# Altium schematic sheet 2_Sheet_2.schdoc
size 322 x 185 mm; Name: A_Customize; Symbol: A_Customize; Device: A_Customize; @Project Name: MyOwnMP3_PCB; REV: 1.0; Date: 2026-02-28; Sheet: 1/1; Draw By: maxyusyuk; Company: Your Company; Convert to PCB: yes; Add into BOM: yes; spicePre: .; @Page No: 2; @Page Count: 3; @Schematic Name: MyOwnMP3; @Board Name: MyOwnMP3; @Update Date: 2026-04-22; @Create Time: 17:18:59; @Update Time: 18:40:26; @Page Name: Sheet_2; @Create Date: 2026-03-28
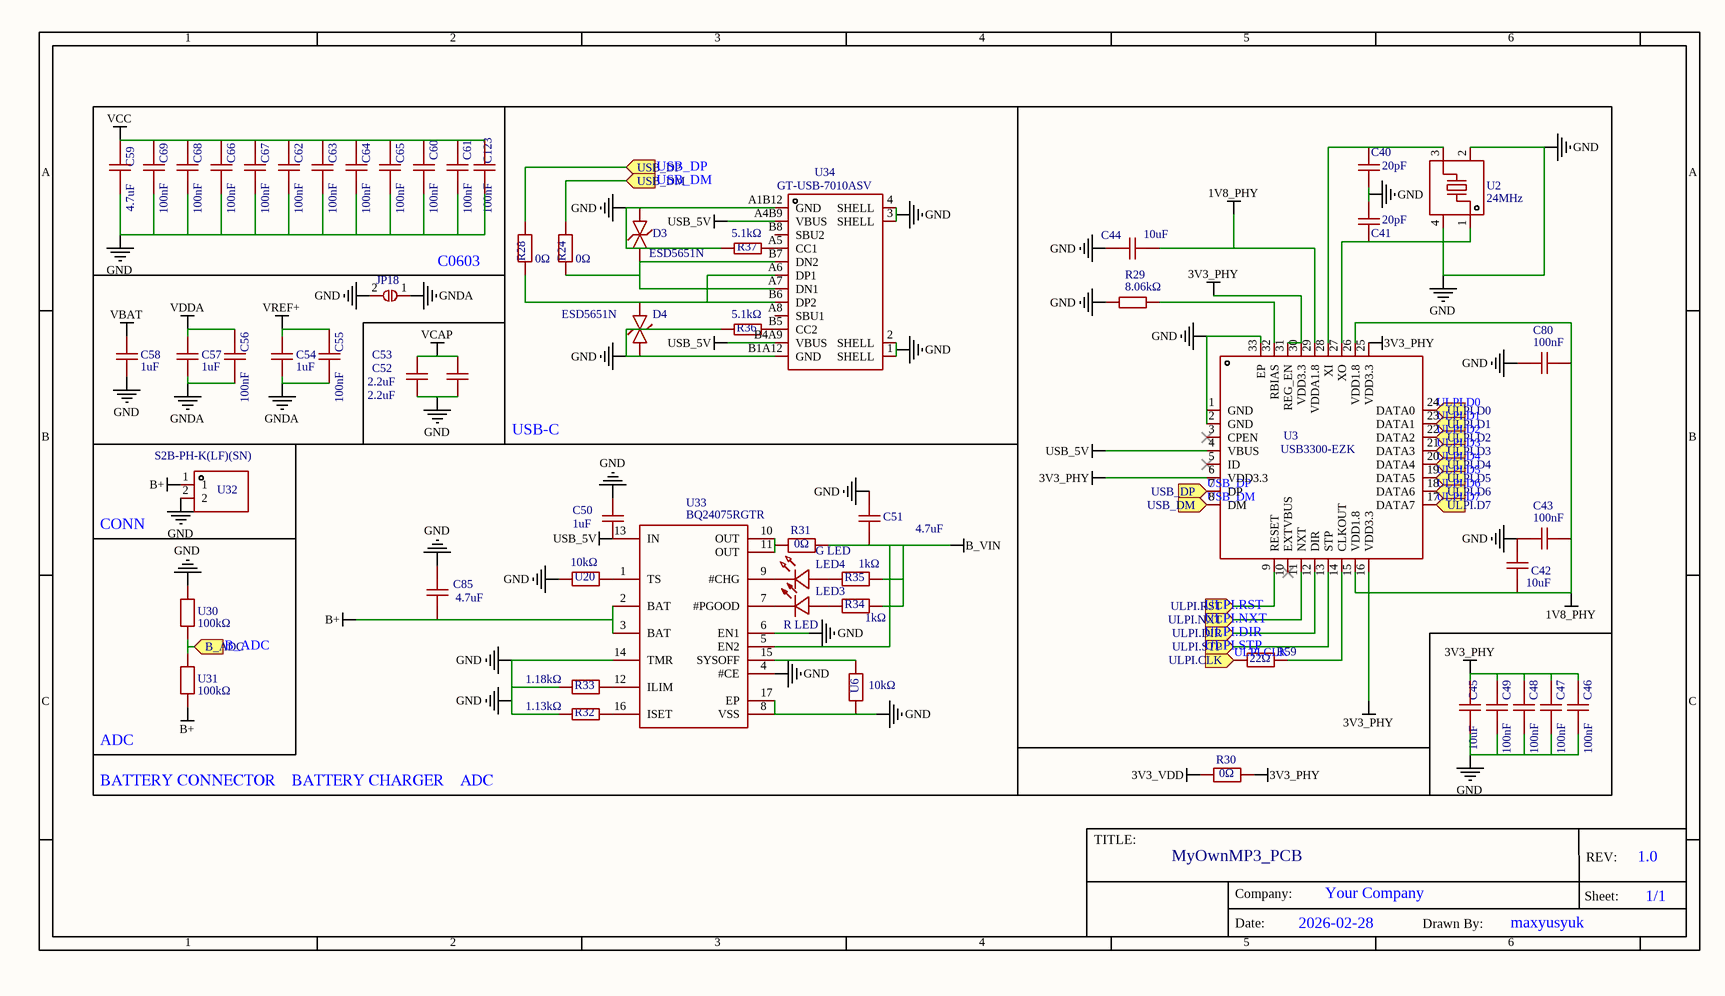
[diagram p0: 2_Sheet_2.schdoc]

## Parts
C40  20pF  [C0603]
C41  20pF  [C0603]
C42  10uF  [C1206]
C43  100nF  [C0603]
C44  10uF  [C1206]
C45  10uF  [C1206]
C46  100nF  [C0603]
C47  100nF  [C0603]
C48  100nF  [C0603]
C49  100nF  [C0603]
C50  1uF  [C0603]
C51  4.7uF  [C0603]
C52  2.2uF  [C0603]
C53  2.2uF  [C0603]
C54  1uF  [C0603]
C55  100nF  [C0603]
C56  100nF  [C0603]
C57  1uF  [C0603]
C58  1uF  [C0603]
C59  4.7uF  [C0603]
C60  100nF  [C0603]
C61  100nF  [C0603]
C62  100nF  [C0603]
C63  100nF  [C0603]
C64  100nF  [C0603]
C65  100nF  [C0603]
C66  100nF  [C0603]
C67  100nF  [C0603]
C68  100nF  [C0603]
C69  100nF  [C0603]
C80  100nF  [C0603]
C85  4.7uF  [C0603]
C123  100nF  [C0603]
D3  ESD5651N  [DFN1006-2L_L1.0-W0.6-ESD5651N]
D4  ESD5651N  [DFN1006-2L_L1.0-W0.6-ESD5651N]
JP18  2P Solder UNBridge Jumper  [SOLDER BRIDGE 2P UNBRIDGED]  (value not drawn)
LED3  R LED  [LED0603-RD_RED]
LED4  G LED  [LED0603-RD_GREEN]
R24  0Ω  [R0603]
R28  0Ω  [R0603]
R29  8.06kΩ  [R0603]
R30  0Ω  [R1206]
R31  0Ω  [R1206]
R32  1.13kΩ  [R0603]
R33  1.18kΩ  [R0603]
R34  1kΩ  [R0603]
R35  1kΩ  [R0603]
R36  5.1kΩ  [R0603]
R37  5.1kΩ  [R0603]
R59  22Ω  [R0603]
U2  24MHz  [OSC-SMD_4P-L2.5-W2.0-BL]
U3  USB3300-EZK  [QFN-32_L5.0-W5.0-P0.50-BL-EP3.4]
U6  10kΩ  [R0603]
U20  10kΩ  [R0603]
U30  100kΩ  [R0603]
U31  100kΩ  [R0603]
U32  S2B-PH-K(LF)(SN)  [CONN-TH_S2B-PH-K-LF-SN]
U33  BQ24075RGTR  [QFN-16_L3.0-W3.0-P0.50-TL-EP1.7]
U34  GT-USB-7010ASV  [USB-C-SMD_G-SWITCH_GT-USB-7010ASV]

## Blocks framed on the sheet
USB-C: C59-C69 C123 D3 D4 R24 R28 R36 R37 U34
C0603: C52-C58 JP18
BATTERY CONNECTOR  BATTERY CHARGER  ADC: C50 C51 C85 LED3 LED4 R31-R35 U6 U20 U33
CONN: U32
ADC: U30 U31

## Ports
B_ADC (in), ULPI.CLK (in), ULPI.D0 (in), ULPI.D1 (in), ULPI.D2 (in), ULPI.D3 (in), ULPI.D4 (in), ULPI.D5 (in), ULPI.D6 (in), ULPI.D7 (in), ULPI.DIR (in), ULPI.NXT (in), ULPI.RST (in), ULPI.STP (in), USB_DM (in), USB_DP (in)

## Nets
1V8_PHY: C42.2 C43.2 C44.2 C80.2 U3.15(VDD1.8) U3.26(VDD1.8) U3.29(VDDA1.8)
3V3_PHY: C45.2 C46.1 C47.1 C48.1 C49.1 R30.2 U3.6(VDD3.3) U3.16(VDD3.3) U3.25(VDD3.3) U3.30(VDD3.3) U3.31(REG_EN)
3V3_VDD: R30.1
B+: C85.2 U31.2 U32.1 U33.2(BAT) U33.3(BAT)
B_VIN: C51.2 R31.2 R34.1 R35.1 U33.5(EN2)
GND: C40.1 C41.2 C42.1 C43.1 C44.1 C45.1 C46.2 C47.2 C48.2 C49.2 C50.1 C51.1 C52.1 C53.1 C58.1 C59.1 C60.2 C61.2 C62.2 C63.2 C64.2 C65.2 C66.2 C67.2 C68.2 C69.2 C80.1 C85.1 C123.2 D3.1 D4.1 JP18.2(B) R29.1 R32.1 R33.1 R36.1 R37.1 U2.2(GND) U2.4(GND) U3.1(GND) U3.2(GND) U3.33(EP) U6.1 U20.1 U30.1 U32.2 U33.4(#CE) U33.6(EN1) U33.8(VSS) U33.14(TMR) U33.17(EP) U34.1(SHELL) U34.2(SHELL) U34.3(SHELL) U34.4(SHELL) U34.A1B12(GND) U34.B1A12(GND)
GNDA: C54.1 C55.2 C56.2 C57.1 JP18.1(A)
USB_5V: C50.2 U3.4(VBUS) U33.13(IN) U34.A4B9(VBUS) U34.B4A9(VBUS)
VBAT: C58.2
VCAP: C52.2 C53.2
VCC: C59.2 C60.1 C61.1 C62.1 C63.1 C64.1 C65.1 C66.1 C67.1 C68.1 C69.1 C123.1
VDDA: C56.1 C57.2
VREF+: C54.2 C55.1
B_ADC: U30.2 U31.1 ; port B_ADC
ULPI.CLK: R59.1 ; port ULPI.CLK
ULPI.D0: U3.24(DATA0) ; port ULPI.D0
ULPI.D1: U3.23(DATA1) ; port ULPI.D1
ULPI.D2: U3.22(DATA2) ; port ULPI.D2
ULPI.D3: U3.21(DATA3) ; port ULPI.D3
ULPI.D4: U3.20(DATA4) ; port ULPI.D4
ULPI.D5: U3.19(DATA5) ; port ULPI.D5
ULPI.D6: U3.18(DATA6) ; port ULPI.D6
ULPI.D7: U3.17(DATA7) ; port ULPI.D7
ULPI.DIR: U3.12(DIR) ; port ULPI.DIR
ULPI.NXT: U3.11(NXT) ; port ULPI.NXT
ULPI.RST: U3.9(RESET) ; port ULPI.RST
ULPI.STP: U3.13(STP) ; port ULPI.STP
USB_DM: R24.1 U3.8(DM) ; port USB_DM
USB_DP: R28.2 U3.7(DP) ; port USB_DP
NetC40_2: C40.2 U2.3 U3.28(XI)
NetC41_1: C41.1 U2.1 U3.27(XO)
NetD3_2: D3.2 R24.2 U34.A7(DN1) U34.B7(DN2)
NetD4_2: D4.2 R28.1 U34.A6(DP1) U34.B6(DP2)
NetLED3_1: LED3.1(-) U33.7(#PGOOD)
NetLED3_2: LED3.2(+) R34.2
NetLED4_1: LED4.1(C) U33.9(#CHG)
NetLED4_2: LED4.2(A) R35.2
NetR29_2: R29.2 U3.32(RBIAS)
NetR31_1: R31.1 U33.10(OUT) U33.11(OUT)
NetR32_2: R32.2 U33.16(ISET)
NetR33_2: R33.2 U33.12(ILIM)
NetR36_2: R36.2 U34.B5(CC2)
NetR37_2: R37.2 U34.A5(CC1)
NetR59_2: R59.2 U3.14(CLKOUT)
NetU6_2: U6.2 U33.15(SYSOFF)
NetU20_2: U20.2 U33.1(TS)

Not connected (* = marked no-connect by the designer): U3 3(CPEN)* 5(ID)* 10(EXTVBUS)*; U34 A8(SBU1) B8(SBU2)

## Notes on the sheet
- Labels drawn without touching a wire or pin: B_ADC, ULPI.DIR, ULPI.NXT, ULPI.RST, ULPI.STP, USB_DM, USB_DP

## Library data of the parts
C40 C41 = 20pF: Manufacturer: YAGEO(国巨); Manufacturer Part: CC0603JRNPO9BN200; Convert to PCB: yes; nameAlias: Value
C42 C44 C45 = 10uF: Manufacturer: CCTC(三环); Manufacturer Part: TCC1206X7R106K160HT; Convert to PCB: yes; nameAlias: Value; Contributor: LCSC
C43 C46-C49 C55 C56 C60-C69 C80 C123 = 100nF: Manufacturer: YAGEO(国巨); Manufacturer Part: CC0603JRX7R8BB104; Convert to PCB: yes; nameAlias: Value; Contributor: LCSC
C50 C54 C57 C58 = 1uF: Manufacturer Part: CC0603KRX5R8BB105; Manufacturer: YAGEO(国巨); Convert to PCB: yes; nameAlias: Value
C51 C59 C85 = 4.7uF: Manufacturer: CCTC(三环); Manufacturer Part: TCC0603X5R475K100CT; Convert to PCB: yes; nameAlias: Value; Contributor: LCSC
C52 C53 = 2.2uF: Manufacturer: YAGEO(国巨); Manufacturer Part: CC0603KRX5R7BB225; Convert to PCB: yes; nameAlias: Value
D3 D4 = ESD5651N: Manufacturer: Leiditech(雷卯电子); Convert to PCB: yes; Contributor: lcsc
JP18 = 2P Solder UNBridge Jumper: Manufacturer Part: DNP; Convert to PCB: yes; Add into BOM: no; Contributor: RonNovy
LED3 = R LED: Manufacturer: TUOZHAN(拓展光电); Manufacturer Part: TZ-P2-0603RTCS2-0.6T; Convert to PCB: yes; Contributor: LCSC
LED4 = G LED: Manufacturer: TUOZHAN(拓展光电); Manufacturer Part: F.0603.00025/P2-0603G1TS2-06T-002; Convert to PCB: yes; Contributor: lcsc
R24 R28 = 0Ω: Manufacturer: Walsin(华新科); Manufacturer Part: WR06X000 PTL; Convert to PCB: yes; nameAlias: Value; Contributor: lcsc
R29 = 8.06kΩ: Manufacturer: Tyohm(幸亚电阻); Manufacturer Part: RMC06038.06K1%N; Convert to PCB: yes; nameAlias: Value; Contributor: LCSC
R30 R31 = 0Ω: Manufacturer: JIERR(捷而瑞); Manufacturer Part: JER1206F1R000; Convert to PCB: yes; nameAlias: Value; Contributor: lcsc
R32 = 1.13kΩ: Manufacturer: YAGEO(国巨); Manufacturer Part: RC0603FR-071K13L; Convert to PCB: yes; nameAlias: Value
R33 = 1.18kΩ: Manufacturer: VO(翔胜); Manufacturer Part: SCR0603F1K18; Convert to PCB: yes; nameAlias: Value; Contributor: lcsc
R34 R35 = 1kΩ: Manufacturer: FOJAN(富捷); Manufacturer Part: FRR0603F1001TS; Convert to PCB: yes; nameAlias: Value; Contributor: lcsc
R36 R37 = 5.1kΩ: Manufacturer: Tyohm(幸亚电阻); Manufacturer Part: RMC06035.1K1%N; Convert to PCB: yes; nameAlias: Value; Contributor: LCSC
R59 = 22Ω: Manufacturer: YAGEO(国巨); Manufacturer Part: SR0603FR-7T22RL; Convert to PCB: yes; nameAlias: Value; Contributor: lcsc
U2 = 24MHz: Manufacturer: SCTF(星通时频); Manufacturer Part: SX2B24.000F1210F30; Convert to PCB: yes; nameAlias: Value; Contributor: lcsc
U3 = USB3300-EZK: Manufacturer: MICROCHIP(美国微芯); Convert to PCB: yes
U6 U20 = 10kΩ: Manufacturer: RESI(开步睿思); Manufacturer Part: PTFR0603B10K0N9; Convert to PCB: yes; nameAlias: Value; Contributor: lcsc
U30 U31 = 100kΩ: Manufacturer: VO(翔胜); Manufacturer Part: SCR0603F100K; Convert to PCB: yes; Contributor: lcsc; nameAlias: Value
U32 = S2B-PH-K(LF)(SN): Manufacturer: JST; Convert to PCB: yes; Contributor: LCSC
U33 = BQ24075RGTR: Manufacturer: TI(德州仪器); Convert to PCB: yes
U34 = GT-USB-7010ASV: Manufacturer: G-Switch(品赞); Convert to PCB: yes; Contributor: lcsc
